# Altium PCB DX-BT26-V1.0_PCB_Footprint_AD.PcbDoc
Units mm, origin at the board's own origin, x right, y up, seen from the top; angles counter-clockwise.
Board outline 152.4 x 101.6 mm, 2 copper layers (Top, Bottom), stack 0.323 mm thick; 1 components, 0 nets, 34 pads, 0 vias.
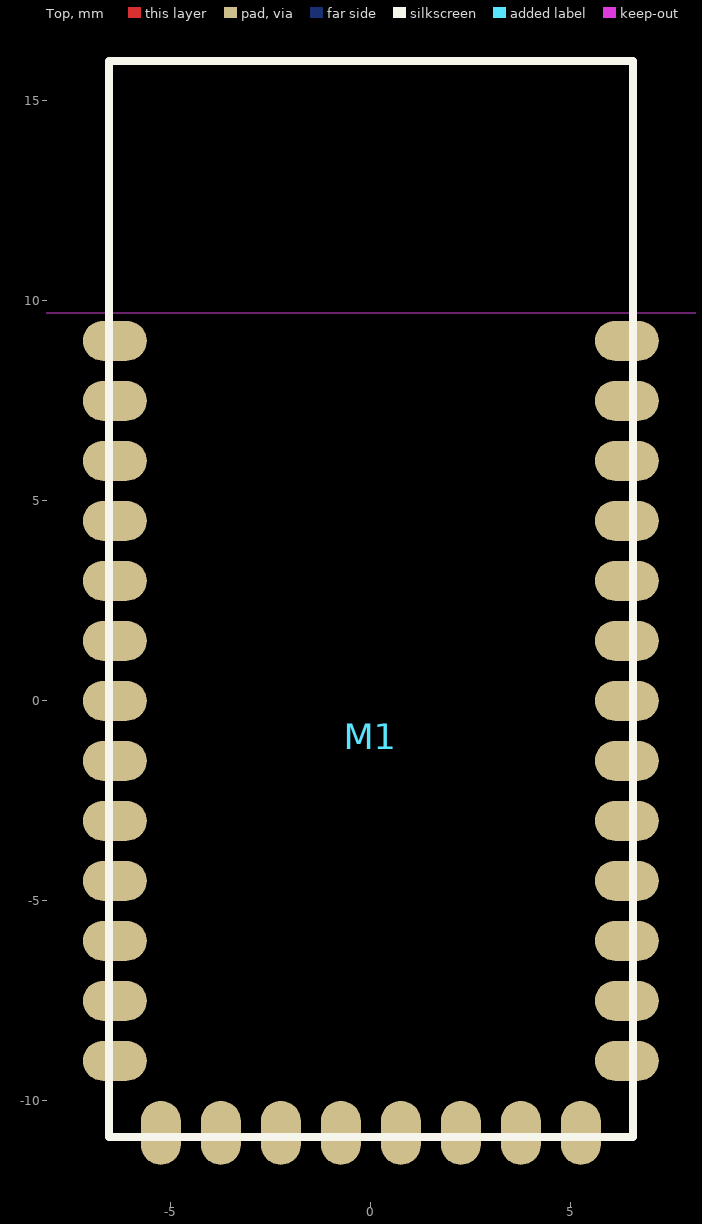
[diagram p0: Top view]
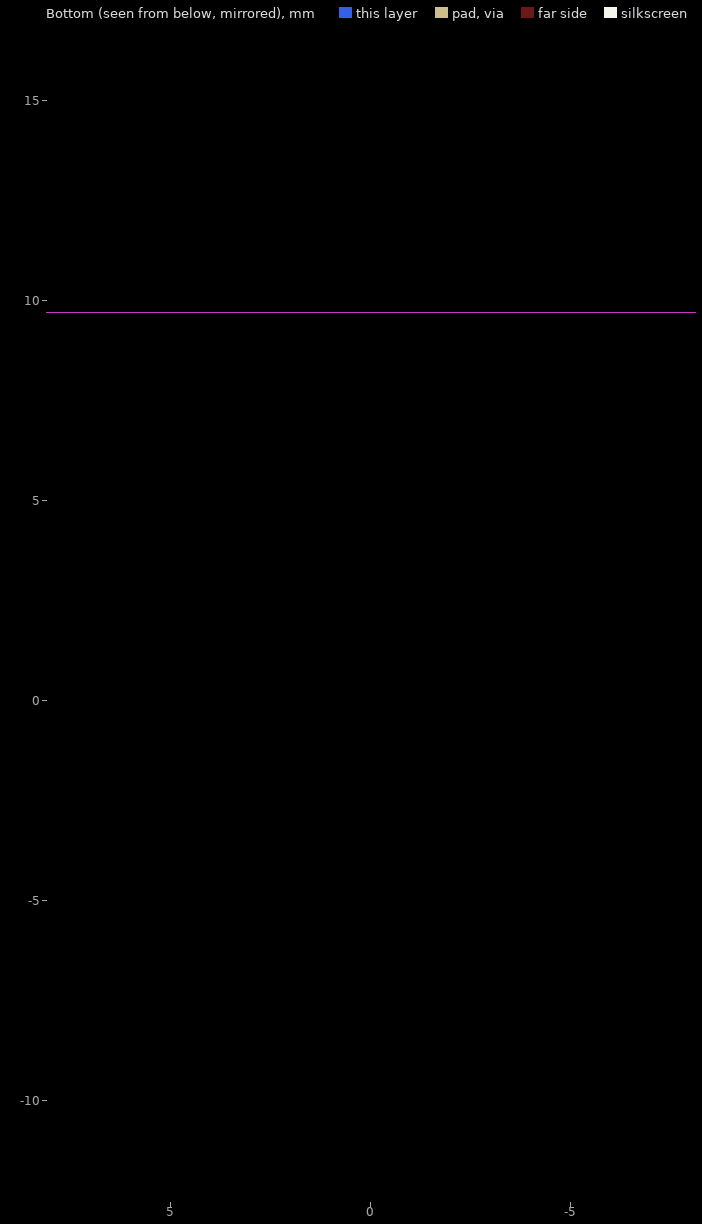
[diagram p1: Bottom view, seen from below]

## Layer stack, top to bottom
Solder Mask Top: solder mask 0.0102, Solder Resist, Dk 3.5
Top: signal copper 0.0343
Dielectric 1: dielectric 0.254, FR-4, Dk 4.3
Bottom: signal copper 0.0343
Solder Mask Bottom: solder mask 0.0102, Solder Resist, Dk 3.5

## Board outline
-694.363,-676.631 -541.963,-676.631 -541.963,-575.031 -694.363,-575.031

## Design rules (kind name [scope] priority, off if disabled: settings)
Clearance "'Default' PADS rule_17" [All] p1: gap=0.152 ignorepadtopadclearanceinfootprint=FALSE except(0: Arc-Hole Track-Hole SMDPad-Hole THPad-Hole Via-Hole Fill-Hole Poly-Hole Region-Hole Text-Hole)
Clearance "'Default' PADS rule_16" [InPolygon vs InPolygon] p2: gap=0.2 ignorepadtopadclearanceinfootprint=FALSE except(0: Arc-Hole Track-Hole SMDPad-Hole THPad-Hole Via-Hole Fill-Hole Poly-Hole Region-Hole Text-Hole)
Clearance "'Default' PADS rule_15" [All] p3: gap=0.152 ignorepadtopadclearanceinfootprint=FALSE except(0: Arc-Hole Track-Hole SMDPad-Hole THPad-Hole Via-Hole Fill-Hole Poly-Hole Region-Hole Text-Hole)
ComponentClearance "'Default' PADS rule_12" [All] p1: gap=0 collisioncheckmode=3 verticalgap=0.254 showdistances=FALSE
FlightTimeFalling "'Default' PADS rule_10" [All] p1: maximum=10.00
FlightTimeRising "'Default' PADS rule_9" [All] p1: maximum=10.00
Length "'Default' PADS rule_5" [All] p1: maxlimit=1270 minlimit=0
MatchedLengths "'Default' PADS rule_11" [InNetClass('All Nets')] p1: tolerance=5.08 checknetsindiffpair=TRUE checkdiffpairvsdiffpair=FALSE checkxsignals=FALSE checkothers=FALSE
MaxMinImpedance "'Default' PADS rule_8" [All] p1: minimum=50.00 maximum=150.0
ParallelSegment "'Default' PADS rule_7" [All] p1: limit=25.4 gap=5.08
ParallelSegment "'Default' PADS rule_6" [All] p2: limit=25.4 gap=5.08
PlaneClearance "'Default' PADS rule_14" [All] p1: clearance=0.2
PlaneConnect "Power Plane Connect Style - Via from round thru-hole global defaults" [IsVia] p1: planeconnectstyle=Direct reliefexpansion=0.508 reliefentries=4 reliefconductorwidth=0.381 reliefairgap=0.254
PlaneConnect "Power Plane Connect Style - Round thru-hole pad from global defaults" [IsPad And OnMultiLayer And (PadShape_MidLayer1 = 'Round') And (PadXSize_MidLayer1 = PadYSize_MidLayer1)] p2: planeconnectstyle=Direct reliefexpansion=0.508 reliefentries=4 reliefconductorwidth=0.381 reliefairgap=0.254
PlaneConnect "Power Plane Connect Style - Square thru-hole pad from global defaults" [IsPad And OnMultiLayer And ((PadShape_MidLayer1 = 'Rectangular') Or (PadShape_MidLayer1 = 'Octagonal') Or (PadShape_MidLayer1 = 'Rounded Rectangle')) And (PadXSize_MidLayer1 = PadYSize_MidLayer1)] p3: planeconnectstyle=Direct reliefexpansion=0.508 reliefentries=4 reliefconductorwidth=0.381 reliefairgap=0.254
PlaneConnect "Power Plane Connect Style - Rect thru-hole pad from global defaults" [IsPad And OnMultiLayer And ((PadShape_MidLayer1 = 'Rectangular') Or (PadShape_MidLayer1 = 'Octagonal') Or (PadShape_MidLayer1 = 'Rounded Rectangle')) And (PadXSize_MidLayer1 <> PadYSize_MidLayer1)] p4: planeconnectstyle=Direct reliefexpansion=0.508 reliefentries=4 reliefconductorwidth=0.381 reliefairgap=0.254
PlaneConnect "Power Plane Connect Style - Square-rect thru-hole pad from global defaults" [IsPad And OnMultiLayer And (PadShape_MidLayer1 = 'Rounded Rectangle') And (PadXSize_MidLayer1 = PadYSize_MidLayer1) And (Pad_CornerRadius_MidLayer1 = '0%')] p5: planeconnectstyle=Direct reliefexpansion=0.508 reliefentries=4 reliefconductorwidth=0.381 reliefairgap=0.254
PlaneConnect "Power Plane Connect Style - Oval thru-hole pad from global defaults" [IsPad And OnMultiLayer And (PadShape_MidLayer1 = 'Round') And (PadXSize_MidLayer1 <> PadYSize_MidLayer1)] p6: planeconnectstyle=Direct reliefexpansion=0.508 reliefentries=4 reliefconductorwidth=0.381 reliefairgap=0.254
PlaneConnect "Power Plane Connect Style - Round-oval thru-hole pad from global defaults" [IsPad And OnMultiLayer And (PadShape_MidLayer1 = 'Rounded Rectangle') And (PadXSize_MidLayer1 = PadYSize_MidLayer1) And (Pad_CornerRadius_MidLayer1 = '100%')] p7: planeconnectstyle=Direct reliefexpansion=0.508 reliefentries=4 reliefconductorwidth=0.381 reliefairgap=0.254
PolygonConnect "Polygon Connect Style - Bottom Round SMD from global defaults" [IsSMTPin And (PadShape_BottomLayer = 'Round') And (PadXSize_BottomLayer = PADYSize_BottomLayer) vs Layer = 'Bottom'] p1: connectstyle=Direct reliefconductorwidth=0.254 reliefentries=4 polygonreliefangle="45 Angle" airgapwidth=0.254
PolygonConnect "Polygon Connect Style - Top Round SMD from global defaults" [IsSMTPin And (PadShape_TopLayer = 'Round') And (PadXSize_TopLayer = PADYSize_TopLayer) vs Layer = 'Top'] p2: connectstyle=Direct reliefconductorwidth=0.254 reliefentries=4 polygonreliefangle="45 Angle" airgapwidth=0.254
PolygonConnect "Polygon Connect Style - Bottom Square SMD from global defaults 1" [IsSMTPin And (PadShape_BottomLayer = 'Rectangular') And (PadXSize_BottomLayer = PADYSize_BottomLayer) vs Layer = 'Bottom'] p3: connectstyle=Direct reliefconductorwidth=0.254 reliefentries=4 polygonreliefangle="45 Angle" airgapwidth=0.254
PolygonConnect "Polygon Connect Style - Bottom Square SMD from global defaults 2" [IsSMTPin And (PadShape_BottomLayer = 'Octagonal') And (PadXSize_BottomLayer = PADYSize_BottomLayer) vs Layer = 'Bottom'] p4: connectstyle=Direct reliefconductorwidth=0.254 reliefentries=4 polygonreliefangle="45 Angle" airgapwidth=0.254
PolygonConnect "Polygon Connect Style - Bottom Square SMD from global defaults 3" [IsSMTPin And (PadShape_BottomLayer = 'Rounded Rectangle') And (PadXSize_BottomLayer = PADYSize_BottomLayer) vs Layer = 'Bottom'] p5: connectstyle=Direct reliefconductorwidth=0.254 reliefentries=4 polygonreliefangle="45 Angle" airgapwidth=0.254
PolygonConnect "Polygon Connect Style - Top Square SMD from global defaults 1" [IsSMTPin And (PadShape_TopLayer = 'Rectangular') And (PadXSize_TopLayer = PADYSize_TopLayer) vs Layer = 'Top'] p6: connectstyle=Direct reliefconductorwidth=0.254 reliefentries=4 polygonreliefangle="45 Angle" airgapwidth=0.254
PolygonConnect "Polygon Connect Style - Top Square SMD from global defaults 2" [IsSMTPin And (PadShape_TopLayer = 'Octagonal') And (PadXSize_TopLayer = PADYSize_TopLayer) vs Layer = 'Top'] p7: connectstyle=Direct reliefconductorwidth=0.254 reliefentries=4 polygonreliefangle="45 Angle" airgapwidth=0.254
PolygonConnect "Polygon Connect Style - Top Square SMD from global defaults 3" [IsSMTPin And (PadShape_TopLayer = 'Rounded Rectangle') And (PadXSize_TopLayer = PADYSize_TopLayer) vs Layer = 'Top'] p8: connectstyle=Direct reliefconductorwidth=0.254 reliefentries=4 polygonreliefangle="45 Angle" airgapwidth=0.254
PolygonConnect "Polygon Connect Style - Bottom Rect SMD from global defaults 1" [IsSMTPin And (PadShape_BottomLayer = 'Rectangular') And (PadXSize_BottomLayer <> PADYSize_BottomLayer) vs Layer = 'Bottom'] p9: connectstyle=Direct reliefconductorwidth=0.254 reliefentries=4 polygonreliefangle="45 Angle" airgapwidth=0.254
PolygonConnect "Polygon Connect Style - Bottom Rect SMD from global defaults 2" [IsSMTPin And (PadShape_BottomLayer = 'Octagonal') And (PadXSize_BottomLayer <> PADYSize_BottomLayer) vs Layer = 'Bottom'] p10: connectstyle=Direct reliefconductorwidth=0.254 reliefentries=4 polygonreliefangle="45 Angle" airgapwidth=0.254
PolygonConnect "Polygon Connect Style - Bottom Rect SMD from global defaults 3" [IsSMTPin And (PadShape_BottomLayer = 'Rounded Rectangle') And (PadXSize_BottomLayer <> PADYSize_BottomLayer) vs Layer = 'Bottom'] p11: connectstyle=Direct reliefconductorwidth=0.254 reliefentries=4 polygonreliefangle="45 Angle" airgapwidth=0.254
PolygonConnect "Polygon Connect Style - Bottom Square-rect SMD pad from global defaults" [IsSMTPin And (PadShape_BottomLayer = 'Rounded Rectangle') And (PadXSize_BottomLayer = PADYSize_BottomLayer) And (Pad_CornerRadius_BottomLayer = '0%') vs Layer = 'Bottom'] p12: connectstyle=Direct reliefconductorwidth=0.254 reliefentries=4 polygonreliefangle="45 Angle" airgapwidth=0.254
PolygonConnect "Polygon Connect Style - Top Rect SMD from global defaults 1" [IsSMTPin And (PadShape_TopLayer = 'Rectangular') And (PadXSize_TopLayer <> PADYSize_TopLayer) vs Layer = 'Top'] p13: connectstyle=Direct reliefconductorwidth=0.254 reliefentries=4 polygonreliefangle="45 Angle" airgapwidth=0.254
PolygonConnect "Polygon Connect Style - Top Rect SMD from global defaults 2" [IsSMTPin And (PadShape_TopLayer = 'Octagonal') And (PadXSize_TopLayer <> PADYSize_TopLayer) vs Layer = 'Top'] p14: connectstyle=Direct reliefconductorwidth=0.254 reliefentries=4 polygonreliefangle="45 Angle" airgapwidth=0.254
PolygonConnect "Polygon Connect Style - Top Rect SMD from global defaults 3" [IsSMTPin And (PadShape_TopLayer = 'Rounded Rectangle') And (PadXSize_TopLayer <> PADYSize_TopLayer) vs Layer = 'Top'] p15: connectstyle=Direct reliefconductorwidth=0.254 reliefentries=4 polygonreliefangle="45 Angle" airgapwidth=0.254
PolygonConnect "Polygon Connect Style - Top Square-rect SMD pad from global defaults" [IsSMTPin And (PadShape_TopLayer = 'Rounded Rectangle') And (PadXSize_TopLayer = PADYSize_TopLayer) And (Pad_CornerRadius_TopLayer = '0%') vs Layer = 'Top'] p16: connectstyle=Direct reliefconductorwidth=0.254 reliefentries=4 polygonreliefangle="45 Angle" airgapwidth=0.254
PolygonConnect "Polygon Connect Style - Bottom Oval SMD from global defaults" [IsSMTPin And (PadShape_BottomLayer = 'Round') And (PadXSize_BottomLayer <> PADYSize_BottomLayer) vs Layer = 'Bottom'] p17: connectstyle=Direct reliefconductorwidth=0.254 reliefentries=4 polygonreliefangle="45 Angle" airgapwidth=0.254
PolygonConnect "Polygon Connect Style - Bottom Round-oval SMD pad from global defaults" [IsSMTPin And (PadShape_BottomLayer = 'Rounded Rectangle') And (PadXSize_BottomLayer = PADYSize_BottomLayer) And (Pad_CornerRadius_BottomLayer = '100%') vs Layer = 'Bottom'] p18: connectstyle=Direct reliefconductorwidth=0.254 reliefentries=4 polygonreliefangle="45 Angle" airgapwidth=0.254
PolygonConnect "Polygon Connect Style - Top Oval SMD from global defaults" [IsSMTPin And (PadShape_TopLayer = 'Round') And (PadXSize_TopLayer <> PADYSize_TopLayer) vs Layer = 'Top'] p19: connectstyle=Direct reliefconductorwidth=0.254 reliefentries=4 polygonreliefangle="45 Angle" airgapwidth=0.254
PolygonConnect "Polygon Connect Style - Top Round-oval SMD pad from global defaults" [IsSMTPin And (PadShape_TopLayer = 'Rounded Rectangle') And (PadXSize_TopLayer = PADYSize_TopLayer) And (Pad_CornerRadius_TopLayer = '100%') vs Layer = 'Top'] p20: connectstyle=Direct reliefconductorwidth=0.254 reliefentries=4 polygonreliefangle="45 Angle" airgapwidth=0.254
PolygonConnect "Polygon Connect Style - Via from round thru-hole global defaults_18" [IsVia] p21: connectstyle=Direct reliefconductorwidth=0.381 reliefentries=4 polygonreliefangle="45 Angle" airgapwidth=0.254
PolygonConnect "Polygon Connect Style - Bottom Round thru-hole pad from global defaults" [IsPad And OnMultiLayer And (PadShape_BottomLayer = 'Round') And (PadXSize_BottomLayer = PADYSize_BottomLayer) vs Layer = 'Bottom'] p22: connectstyle=Direct reliefconductorwidth=0.381 reliefentries=4 polygonreliefangle="45 Angle" airgapwidth=0.254
PolygonConnect "Polygon Connect Style - Via from round thru-hole global defaults" [IsVia] p23: connectstyle=Direct reliefconductorwidth=0.381 reliefentries=4 polygonreliefangle="45 Angle" airgapwidth=0.254
PolygonConnect "Polygon Connect Style - Top Round thru-hole pad from global defaults" [IsPad And OnMultiLayer And (PadShape_TopLayer = 'Round') And (PadXSize_TopLayer = PADYSize_TopLayer) vs Layer = 'Top'] p24: connectstyle=Direct reliefconductorwidth=0.381 reliefentries=4 polygonreliefangle="45 Angle" airgapwidth=0.254
PolygonConnect "Polygon Connect Style - Bottom Square thru-hole pad from global defaults" [IsPad And OnMultiLayer And ((PadShape_BottomLayer = 'Rectangular') Or (PadShape_BottomLayer = 'Octagonal') Or (PadShape_BottomLayer = 'Rounded Rectangle')) And (PadXSize_BottomLayer = PADYSize_BottomLayer) vs Layer = 'Bottom'] p25: connectstyle=Direct reliefconductorwidth=0.381 reliefentries=4 polygonreliefangle="45 Angle" airgapwidth=0.254
PolygonConnect "Polygon Connect Style - Top Square thru-hole pad from global defaults" [IsPad And OnMultiLayer And ((PadShape_TopLayer = 'Rectangular') Or (PadShape_TopLayer = 'Octagonal') Or (PadShape_TopLayer = 'Rounded Rectangle')) And (PadXSize_TopLayer = PADYSize_TopLayer) vs Layer = 'Top'] p26: connectstyle=Direct reliefconductorwidth=0.381 reliefentries=4 polygonreliefangle="45 Angle" airgapwidth=0.254
PolygonConnect "Polygon Connect Style - Bottom Rect thru-hole pad from global defaults" [IsPad And OnMultiLayer And ((PadShape_BottomLayer = 'Rectangular') Or (PadShape_BottomLayer = 'Octagonal') Or (PadShape_BottomLayer = 'Rounded Rectangle')) And (PadXSize_BottomLayer <> PADYSize_BottomLayer) vs Layer = 'Bottom'] p27: connectstyle=Direct reliefconductorwidth=0.381 reliefentries=4 polygonreliefangle="45 Angle" airgapwidth=0.254
PolygonConnect "Polygon Connect Style - Bottom Square-rect thru-hole pad from global defaults" [IsPad And OnMultiLayer And (PadShape_BottomLayer = 'Rounded Rectangle') And (PadXSize_BottomLayer = PADYSize_BottomLayer) And (Pad_CornerRadius_BottomLayer = '0%') vs Layer = 'Bottom'] p28: connectstyle=Direct reliefconductorwidth=0.381 reliefentries=4 polygonreliefangle="45 Angle" airgapwidth=0.254
PolygonConnect "Polygon Connect Style - Top Rect thru-hole pad from global defaults" [IsPad And OnMultiLayer And ((PadShape_TopLayer = 'Rectangular') Or (PadShape_TopLayer = 'Octagonal') Or (PadShape_TopLayer = 'Rounded Rectangle')) And (PadXSize_TopLayer <> PADYSize_TopLayer) vs Layer = 'Top'] p29: connectstyle=Direct reliefconductorwidth=0.381 reliefentries=4 polygonreliefangle="45 Angle" airgapwidth=0.254
PolygonConnect "Polygon Connect Style - Top Square-rect thru-hole pad from global defaults" [IsPad And OnMultiLayer And (PadShape_TopLayer = 'Rounded Rectangle') And (PadXSize_TopLayer = PADYSize_TopLayer) And (Pad_CornerRadius_TopLayer = '0%') vs Layer = 'Top'] p30: connectstyle=Direct reliefconductorwidth=0.381 reliefentries=4 polygonreliefangle="45 Angle" airgapwidth=0.254
PolygonConnect "Polygon Connect Style - Bottom Oval thru-hole pad from global defaults" [IsPad And OnMultiLayer And (PadShape_BottomLayer = 'Round') And (PadXSize_BottomLayer <> PADYSize_BottomLayer) vs Layer = 'Bottom'] p31: connectstyle=Direct reliefconductorwidth=0.381 reliefentries=4 polygonreliefangle="45 Angle" airgapwidth=0.254
PolygonConnect "Polygon Connect Style - Bottom Round-oval thru-hole pad from global defaults" [IsPad And OnMultiLayer And (PadShape_BottomLayer = 'Rounded Rectangle') And (PadXSize_BottomLayer = PADYSize_BottomLayer) And (Pad_CornerRadius_BottomLayer = '100%') vs Layer = 'Bottom'] p32: connectstyle=Direct reliefconductorwidth=0.381 reliefentries=4 polygonreliefangle="45 Angle" airgapwidth=0.254
PolygonConnect "Polygon Connect Style - Top Oval thru-hole pad from global defaults" [IsPad And OnMultiLayer And (PadShape_TopLayer = 'Round') And (PadXSize_TopLayer <> PADYSize_TopLayer) vs Layer = 'Top'] p33: connectstyle=Direct reliefconductorwidth=0.381 reliefentries=4 polygonreliefangle="45 Angle" airgapwidth=0.254
PolygonConnect "Polygon Connect Style - Top Round-oval thru-hole pad from global defaults" [IsPad And OnMultiLayer And (PadShape_TopLayer = 'Rounded Rectangle') And (PadXSize_TopLayer = PADYSize_TopLayer) And (Pad_CornerRadius_TopLayer = '100%') vs Layer = 'Top'] p34: connectstyle=Direct reliefconductorwidth=0.381 reliefentries=4 polygonreliefangle="45 Angle" airgapwidth=0.254
PolygonConnect [All] p35: connectstyle=Relief reliefconductorwidth=0.254 reliefentries=4 polygonreliefangle="90 Angle" airgapwidth=0.254
RoutingLayers "'Default' PADS rule_3" [All] p1: top layer_v5=TRUE bottom layer_v5=TRUE
RoutingPriority "'Default' PADS rule_2" [All] p1: routingpriority=3
RoutingTopology "'Default' PADS rule" [All] p1: topology=Shortest
RoutingVias "'Default' PADS rule_4" [All] p1: holewidth=0.23 width=0.5 viastyle="Through Hole" minholewidth=0.23 minwidth=0.5 maxholewidth=0.23 maxwidth=0.5
SolderMaskExpansion [All] p1: expansion=0.102
Width "'Default' PADS rule_13" [All] p1: maxlimit=0.152 minlimit=0.152 preferedwidth=0.152
24 further rules are at their usual default settings.

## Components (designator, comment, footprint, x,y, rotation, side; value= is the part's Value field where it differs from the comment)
M1 "DX-BT26" DX-BT26 0,0 r0 top

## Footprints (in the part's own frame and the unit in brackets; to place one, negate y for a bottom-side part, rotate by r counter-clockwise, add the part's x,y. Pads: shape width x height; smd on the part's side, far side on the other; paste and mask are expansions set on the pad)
DX-BT26 [mm] "DX-BT26"
  rrect100% 1.6x1 smd: 1(-6.4,9) 2(-6.4,7.5) 3(-6.4,6) 4(-6.4,4.5) 5(-6.4,3) 6(-6.4,1.5) 7(-6.4,0) 8(-6.4,-1.5) 9(-6.4,-3) 10(-6.4,-4.5) 11(-6.4,-6) 12(-6.4,-7.5) 13(-6.4,-9) 22(6.4,-9) 23(6.4,-7.5) 24(6.4,-6) 25(6.4,-4.5) 26(6.4,-3) 27(6.4,-1.5) 28(6.4,0) 29(6.4,1.5) 30(6.4,3) 31(6.4,4.5) 32(6.4,6) 33(6.4,7.5) 34(6.4,9)
  rrect100% 1x1.6 smd: 14(-5.25,-10.8) 15(-3.75,-10.8) 16(-2.25,-10.8) 17(-0.75,-10.8) 18(0.75,-10.8) 19(2.25,-10.8) 20(3.75,-10.8) 21(5.25,-10.8)
  Keep-Out Layer region: -11.4,22 -11.4,9.7 11.4,9.7 11.4,22
  silkscreen extent -6.55,-10.9 6.55,16

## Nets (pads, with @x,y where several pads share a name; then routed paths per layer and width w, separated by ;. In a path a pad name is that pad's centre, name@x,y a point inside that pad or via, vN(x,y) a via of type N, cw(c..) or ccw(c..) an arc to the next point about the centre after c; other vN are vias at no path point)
pads on no net: M1.1 M1.2 M1.3 M1.4 M1.5 M1.6 M1.7 M1.8 M1.9 M1.10 M1.11 M1.12 M1.13 M1.14 M1.15 M1.16 M1.17 M1.18 M1.19 M1.20 M1.21 M1.22 M1.23 M1.24 M1.25 M1.26 M1.27 M1.28 M1.29 M1.30 M1.31 M1.32 M1.33 M1.34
